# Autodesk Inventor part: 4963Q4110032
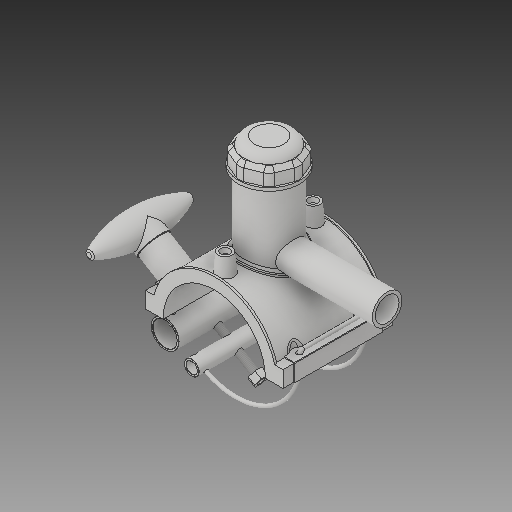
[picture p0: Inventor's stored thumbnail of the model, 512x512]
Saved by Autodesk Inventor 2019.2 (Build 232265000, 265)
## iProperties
Created: 2017-07
Part Number: 4963Q4110032
Material: Generic
Description: PLASSON TAPPING SADDLE 110x32
Document SubType Name: Modeling
Designer: KIM
Mass: 1712.7 g
Surface Area: 2671.49 cm^2
Volume: 1712.7 cm^3
Density: 1 g/cm^3
Appearance: Default
Author: KIM
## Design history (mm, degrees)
derived "4963Q4 (new clamping).ipt"
feature "Solid1::4963Q4 (new clamping).ipt"
feature "Solid2::4963Q4 (new clamping).ipt"
feature "Solid4::4963Q4 (new clamping).ipt"
feature "Solid5::4963Q4 (new clamping).ipt"
feature "Solid6::4963Q4 (new clamping).ipt"
feature "Solid7::4963Q4 (new clamping).ipt"
feature "Solid8::4963Q4 (new clamping).ipt"
feature "Solid9::4963Q4 (new clamping).ipt" dims "d70" = 15
feature "Solid10::4963Q4 (new clamping).ipt"
tag "TaggingFeature1"
body "Solid1"
body "Solid2"
body "Solid3"
body "Solid4"
body "Solid5"
body "Solid6"
body "Solid7"
other parameters: "d2" = 148, "d4" = 118, "d5" = 0, "d6" = 0.1, "d8" = 0, "d19" = 6, "d20" = 6, "d21" = 70.8, "d23" = 0, "d24" = 35.4, "d40" = 68.64, "d41" = 66, "d43" = 0, "d45" = 0, "d47" = 136.8, "d72" = 0, "d73" = 6, "d77" = 5.5, "d78" = 85, "d79" = 15, "d80" = 47.2, "d82" = 5 deg, "d84" = 4, "d85" = 14, "d86" = 0, "d87" = 3, "d88" = 0, "d89" = 1, "d90" = 1, "d91" = 94.4, "d92" = 0, "d93" = 0.5, "d94" = 57.89474, "d96" = 134.64, "d97" = 2.36, "d98" = 0, "d102" = 1.1, "d120" = 140 deg, "d121" = 24.228, "d122" = 20 deg, "d123" = 264, "d124" = 79.2, "d126" = 0, "d143" = 113.3, "d145" = 16.92308, "d149" = 1.65, "d150" = 18.61538, "d153" = 118, "d154" = 0, "d156" = 66, "d157" = 160 deg, "d159" = 4.4, "d161" = 1.65, "d162" = 70.8, "d163" = 0, "d164" = 55, "d167" = 11, "d168" = 64.39024, "d170" = 3.75, "d172" = 0, "d173" = 1, "d175" = 55, "d176" = 20 deg, "d177" = 7.7, "d178" = 22, "d180" = 0, "d183" = 8.8, "d184" = 6.16, "d185" = 38.35, "d186" = 38.35, "d187" = 66, "d188" = 6.6, "d189" = 7.7, "d190" = 0, "d191" = 99, "d193" = 7, "d194" = 4.13, "d195" = 90 deg, "d197" = 0, "d199" = 0, "d200" = 11, "d203" = 114, "d204" = 62.7, "d205" = 46.2, "d206" = 56.1, "d207" = 85.5, "d208" = 88.92, "d209" = 106.02, "d210" = 56.76, "d211" = 66, "d212" = 52.8, "d213" = 0, "d216" = 0, "d217" = 11, "d218" = 11, "d219" = 2.2, "d224" = 0, "d230" = 4.4, "d245" = 35.4, "d246" = 35.4, "d247" = 6, "d248" = 6, "d257" = 71, "d258" = 127, "d259" = 25.6, "d260" = 32, "d263" = 148, "d265" = 0, "d267" = 13.00006, "d268" = 2.60001, "d269" = 2.60001, "d271" = 2.60001, "d273" = 0, "d274" = 23.56194, "d275" = 88, "d277" = 44, "d278" = 176, "d280" = 0, "d283" = 0, "d285" = 0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
